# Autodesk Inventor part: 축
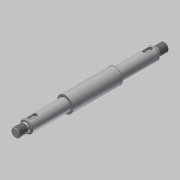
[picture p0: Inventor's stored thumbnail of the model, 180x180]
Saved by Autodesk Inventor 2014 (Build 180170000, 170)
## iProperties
Created: 2018-11
Part Number: 축
Material: 강철, 연강
Document SubType Name: Modeling
Designer: mduedu
Density: 1 g/cm^3
Appearance: 강철
Author: mduedu
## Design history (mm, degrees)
sketch "스케치1"
  geometry: L1 (-35, 0)-(35, 0); L2 (35, 0)-(35, 11); L3 (35, 11)-(-35, 11); L4 (-35, 11)-(-35, 0); L5 (-35, 0)-(-90, 0); L6 (-90, 0)-(-90, 8.5); L7 (-90, 8.5)-(-35, 8.5); L8 (-35, 8.5)-(-35, 0); L9 (-90, 0)-(-105, 0); L10 (-105, 0)-(-105, 6); L11 (-105, 6)-(-90, 6); L12 (-90, 6)-(-90, 0); L13 (0, 0)-(0, 11); L14 (35, 0)-(90, 0); L15 (90, 0)-(90, 8.5); L16 (90, 8.5)-(35, 8.5); L17 (35, 8.5)-(35, 0); L18 (90, 0)-(105, 0); L19 (105, 0)-(105, 6); L20 (105, 6)-(90, 6); L21 (90, 6)-(90, 0); 1 further point
  constraints: 42 end point, 6 parallel, 6 symmetric about line, 3 horizontal, 3 perpendicular, 2 midpoint, 1 coincident
  dimensions: "d0" = 22 diameter of L3 L1; "d2" = 17 diameter of L7 L5; "d3" = 12 diameter of L11 L9; "d4" = 70 distance of L2.end L3.end; "d5" = 55 distance of L6.end L7.end; "d6" = 210 distance between parallel lines of L19 L10
revolve "회전1" sketch "스케치1" stored, may be unused: angle "d7" = 90 deg
fillet "모깎기1" dims "d8" = 0.3
node "작업 평면1"
sketch "스케치2" dims "d11" = 12
  geometry: L1 (15, 2.5)-(22, 2.5); L2 (22, 2.5)-(22, -2.5); L3 (22, -2.5)-(15, -2.5); L4 (15, -2.5)-(15, 2.5); L5 (27.5, 8.5)-(27.5, -8.5) reference; 3 further points
  constraints: 8 end point, 2 midpoint, 2 parallel, 2 vertical alignment, 1 horizontal, 1 horizontal alignment, 1 perpendicular, 4 other
  dimensions: "d9" = 3 dimension on L5; "d10" = 5 distance between parallel lines of L3 L1
extrude "돌출1" cut sketch "스케치2" distance "d12" = 3; taper "d13" = 0 deg
chamfer "모따기1" distance "d14" = 1; stored, may be unused: second distance "d15" = 2, angle "d16" = 45 deg
feature "스레드1" dims "d17" = 12, "d18" = 0
feature "스레드2" dims "d19" = 12, "d20" = 0
chamfer "모따기2" distance "d21" = 1; stored, may be unused: second distance "d22" = 2, angle "d23" = 45 deg
node "솔리드1"
mirror "대칭1"
